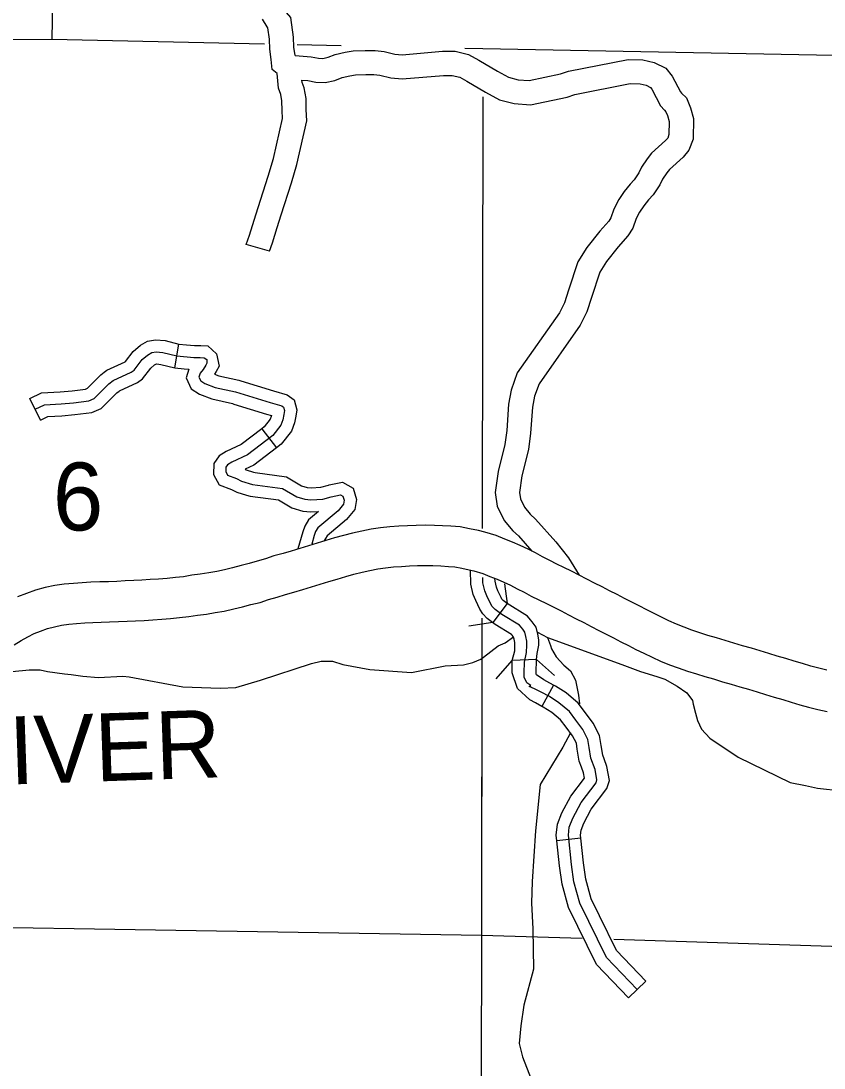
# Model space of a CAD drawing. Extents: x 0 to 3171, y 0 to 2059.
# Drawn here: x 1927.5 to 2010.8, y 478.3 to 586.9 of the extents above; entities that cross this region are included whole.
import ezdxf

# ---------------------------------------------------------------- set-up
doc = ezdxf.new("R2010")
doc.units = 0
for name, color, linetype in [('Level 10', 7, 'Continuous'), ('Level 35', 7, 'Continuous'), ('Level 38', 7, 'Continuous'), ('Level 4', 7, 'Continuous'), ('Level 45', 7, 'Continuous'), ('Level 46', 7, 'Continuous'), ('Level 5', 7, 'Continuous'), ('Level 8', 7, 'Continuous')]:
    doc.layers.add(name, color=color, linetype=linetype)

msp = doc.modelspace()

# ---------------------------------------------------------------- linework, layer by layer
at = {"layer": 'Level 10'}
for p, q in [((1939.18, 528.82), (1939.18, 528.82)), ((1939.41, 524.66), (1939.41, 524.66))]:
    msp.add_line(p, q, dxfattribs=at)
for points in [[(2011.07, 519.52), (2010.23, 519.73), (2009.39, 519.96), (2008.54, 520.21), (2007.67, 520.47), (2006.8, 520.73), (2005.92, 521), (2005.03, 521.27), (2004.14, 521.54), (2003.23, 521.81), (2002.32, 522.07), (2001.42, 522.34), (2000.52, 522.61), (1999.63, 522.88), (1998.73, 523.14), (1997.88, 523.4), (1997.06, 523.68), (1996.25, 523.98), (1995.46, 524.31), (1994.68, 524.65), (1993.92, 525.02), (1993.15, 525.4), (1992.38, 525.8), (1991.61, 526.19), (1990.85, 526.58), (1990.08, 526.97), (1989.31, 527.37), (1988.54, 527.76), (1987.77, 528.16), (1986.98, 528.57), (1986.19, 528.98), (1985.39, 529.4), (1984.59, 529.8), (1983.8, 530.18), (1983.06, 530.54), (1982.33, 530.92), (1981.59, 531.3), (1980.85, 531.69), (1980.08, 532.08), (1979.28, 532.46), (1978.46, 532.81), (1977.68, 533.12), (1976.77, 533.49), (1975.61, 533.83), (1974.94, 534.01), (1974.03, 534.2), (1973.05, 534.38), (1972.09, 534.46), (1971.23, 534.5), (1970.37, 534.54), (1969.43, 534.57), (1968.5, 534.55), (1967.6, 534.51), (1966.69, 534.46), (1965.76, 534.39), (1964.8, 534.28), (1963.82, 534.14), (1962.85, 533.96), (1961.88, 533.74), (1960.95, 533.5), (1960.03, 533.25), (1959.12, 532.98), (1958.22, 532.71), (1957.32, 532.43), (1956.43, 532.15), (1955.53, 531.89), (1954.69, 531.62), (1953.74, 531.38), (1952.87, 531.08), (1952, 530.85), (1951.17, 530.58), (1950.33, 530.38), (1949.45, 530.14), (1948.61, 529.93), (1947.83, 529.75), (1946.98, 529.63), (1946.11, 529.48), (1945.22, 529.37), (1944.35, 529.22), (1943.54, 529.13), (1942.66, 529.05), (1941.79, 528.97), (1940.92, 528.92), (1940.06, 528.86), (1939.2, 528.82)], [(1939.4, 524.66), (1940.3, 524.7), (1941.2, 524.76), (1942.11, 524.82), (1943.03, 524.9), (1943.95, 524.99), (1944.92, 525.09), (1945.82, 525.25), (1946.74, 525.35), (1947.65, 525.52), (1948.59, 525.65), (1949.57, 525.88), (1950.49, 526.11), (1951.36, 526.34), (1952.3, 526.56), (1953.18, 526.85), (1954.09, 527.09), (1954.94, 527.39), (1955.82, 527.61), (1956.75, 527.9), (1957.64, 528.17), (1958.54, 528.45), (1959.43, 528.72), (1960.31, 528.98), (1961.18, 529.24), (1962.03, 529.48), (1962.87, 529.69), (1963.69, 529.88), (1964.5, 530.03), (1965.31, 530.15), (1966.14, 530.24), (1966.97, 530.3), (1967.81, 530.35), (1968.63, 530.38), (1969.41, 530.4), (1970.21, 530.37), (1971.04, 530.34), (1971.82, 530.3), (1972.5, 530.24), (1973.23, 530.11), (1973.99, 529.95), (1974.48, 529.82), (1975.38, 529.55), (1976.12, 529.25), (1976.87, 528.96), (1977.56, 528.66), (1978.25, 528.34), (1978.94, 527.98), (1979.67, 527.61), (1980.41, 527.22), (1981.19, 526.82), (1981.98, 526.43), (1982.74, 526.06), (1983.5, 525.68), (1984.28, 525.28), (1985.06, 524.87), (1985.85, 524.46), (1986.63, 524.06), (1987.41, 523.66), (1988.19, 523.26), (1988.95, 522.87), (1989.71, 522.48), (1990.48, 522.08), (1991.27, 521.69), (1992.08, 521.28), (1992.94, 520.87), (1993.83, 520.47), (1994.74, 520.1), (1995.66, 519.76), (1996.6, 519.44), (1997.53, 519.16), (1998.42, 518.89), (1999.32, 518.62), (2000.24, 518.34), (2001.15, 518.08), (2002.05, 517.81), (2002.94, 517.55), (2003.82, 517.28), (2004.71, 517.01), (2005.59, 516.74), (2006.48, 516.48), (2007.36, 516.21), (2008.26, 515.95), (2009.17, 515.7), (2010.12, 515.47), (2011.09, 515.25)], [(1939.21, 528.82), (1938.31, 528.78), (1937.45, 528.73), (1936.59, 528.71), (1935.69, 528.68), (1934.77, 528.65), (1933.86, 528.59), (1932.95, 528.52), (1932.01, 528.44), (1931.02, 528.3), (1930.01, 528.09), (1929.03, 527.82), (1928.1, 527.5), (1927.15, 527.13)], [(1926.81, 522.17), (1927.53, 522.61), (1928.23, 522.99), (1928.88, 523.33), (1929.55, 523.59), (1930.27, 523.84), (1930.99, 524.04), (1931.72, 524.2), (1932.48, 524.3), (1933.29, 524.37), (1934.14, 524.43), (1934.98, 524.49), (1935.83, 524.52), (1936.71, 524.54), (1937.62, 524.57), (1938.51, 524.62), (1939.38, 524.65)]]:
    msp.add_lwpolyline(points, dxfattribs=at)
at = {"layer": 'Level 35'}
for points in [[(1981.05, 523.48), (1982.1, 522.93), (1989.79, 520.12), (1991.75, 519.41), (1993.42, 518.88), (1994.25, 518.6), (1995.53, 517.89), (1996.53, 517.18), (1997.12, 516.4), (1997.2, 516.01), (1997.45, 515.06), (1997.64, 514.31), (1998.05, 513.43), (1998.93, 512.5), (2001.87, 510.51), (2007.26, 507.88), (2008.84, 507.57), (2010.08, 507.31), (2012.6, 507.02), (2014.93, 507.07), (2016.45, 507.19), (2019.17, 507.95), (2021.33, 509.21)], [(1975.19, 520.69), (1975.48, 520.87), (1976.99, 522.04), (1977.71, 522.37), (1978.57, 522.99)], [(1982.1, 522.93), (1982.42, 522.09), (1982.51, 521.76), (1983, 520.92), (1983.8, 520.04), (1984.48, 519.45), (1984.99, 518.49), (1985.32, 516.94), (1985.4, 516.03)], [(1926.59, 519.41), (1928.35, 519.58), (1929.52, 519.58), (1930.28, 519.41), (1932.04, 519.17), (1932.71, 519.09), (1933.94, 518.9), (1935.55, 518.77), (1938.09, 518.91), (1938.72, 518.86), (1944.31, 517.79), (1948.17, 517.66), (1949.78, 517.73), (1952.34, 518.49), (1957.65, 520.24), (1958.65, 520.48), (1959.81, 520.46), (1960.89, 520.11), (1963.69, 519.6), (1968.01, 519.3), (1971.49, 520), (1973.4, 520.1), (1974.37, 520.33), (1975.19, 520.69)], [(1984.48, 513.02), (1983.7, 511.56), (1981.33, 507.68), (1980.86, 502.87), (1980.52, 497.61), (1980.43, 495.36), (1980.57, 492.71), (1980.64, 488.52), (1979.66, 484.81), (1979.32, 482.64), (1979.17, 480.81), (1979.52, 479.45), (1980.83, 476.04), (1981.37, 473.83), (1981.62, 472.18), (1981.95, 470.65), (1982.6, 468.76)]]:
    msp.add_lwpolyline(points, dxfattribs=at)
at = {"layer": 'Level 38'}
for points in [[(1977.64, 528.47), (1977.92, 526.46)], [(1976.42, 524.46), (1973.95, 524.1)], [(1976.78, 518.65), (1978.45, 520.52)], [(1980.95, 520.65), (1982.81, 518.98)]]:
    msp.add_lwpolyline(points, dxfattribs=at)
at = {"layer": 'Level 4'}
for points in [[(1931.3, 619.32), (1930.73, 584.94)], [(1930.73, 584.94), (1886.47, 584.79)], [(1952.76, 584.45), (1930.73, 584.94)], [(1960.72, 584.28), (1956.16, 584.38)], [(2027.43, 583.03), (2019.09, 583.13), (1975.39, 583.96), (1973.52, 584)]]:
    msp.add_lwpolyline(points, dxfattribs=at)
at = {"layer": 'Level 45'}
for p, q in [((1943.47, 550.88), (1943.89, 553.35)), ((1929.53, 545.45), (1928.44, 547.7)), ((1952.48, 544.57), (1954, 542.58)), ((1977.92, 526.46), (1976.42, 524.46)), ((1980.95, 520.65), (1978.45, 520.52)), ((1982.71, 517.98), (1981.52, 515.78)), ((1985.55, 502.12), (1983.07, 501.85)), ((1992.3, 487.28), (1990.5, 485.55))]:
    msp.add_line(p, q, dxfattribs=at)
for points in [[(1936.13, 550.42), (1936.42, 550.65), (1938.32, 551.52), (1938.36, 551.55), (1939.15, 552.59), (1939.91, 553.23), (1940.63, 553.65), (1941.47, 553.8), (1942.45, 553.72), (1943.89, 553.35), (1944.68, 553.28)], [(1944.68, 553.28), (1945.5, 553.21), (1946.16, 553.21), (1946.9, 553.15), (1947.77, 552.34), (1948.05, 551.04), (1947.75, 550.51), (1947.57, 550.23), (1948.02, 550.06), (1950.09, 549.59), (1950.32, 549.52)], [(1928.99, 546.58), (1929.97, 547.05), (1931.67, 547.14), (1932.95, 547.27), (1934.55, 547.46), (1935.11, 547.71), (1936.63, 549.22), (1937.08, 549.57), (1938.95, 550.43), (1939.25, 550.65), (1940.07, 551.73), (1940.63, 552.21), (1941.07, 552.46), (1941.53, 552.54), (1942.24, 552.48), (1943.68, 552.12), (1945.45, 551.96), (1946.11, 551.96), (1946.52, 551.93), (1946.8, 551.76), (1946.8, 551.36), (1946.69, 551.16), (1946.39, 550.71), (1946.1, 550.34), (1945.97, 549.93), (1946.15, 549.55), (1946.59, 549.27), (1947.66, 548.86), (1949.76, 548.38), (1953.34, 547.29), (1954.57, 546.94), (1954.73, 546.82), (1954.82, 546.47), (1954.77, 546.06), (1954.67, 545.5), (1954.46, 544.95), (1953.61, 543.86), (1951, 541.85), (1949.38, 541.1), (1948.93, 540.83), (1948.75, 540.57), (1948.74, 540.12), (1948.94, 539.77), (1949.85, 539.42), (1950.38, 539.14), (1951.52, 538.8), (1954.64, 538.38), (1956.1, 537.5), (1956.95, 537.25), (1957.58, 537.2), (1958.81, 537.26), (1959.68, 537.52), (1960.63, 537.7), (1960.89, 537.56), (1961.01, 537.15), (1960.94, 536.73), (1960.39, 536.05), (1958.3, 534.3), (1958.06, 533.9), (1957.91, 533.5), (1957.67, 532.61)], [(1937.68, 548.46), (1937.73, 548.5), (1939.59, 549.35), (1940.13, 549.75), (1940.98, 550.86), (1941.36, 551.18), (1941.5, 551.27), (1941.59, 551.28), (1942.03, 551.24), (1943.47, 550.88), (1944.45, 550.79)], [(1944.45, 550.79), (1944.92, 550.75), (1944.63, 549.84), (1945.17, 548.69), (1946.02, 548.15), (1947.3, 547.66), (1949.44, 547.17), (1949.59, 547.13)], [(1928.44, 547.7), (1929.65, 548.29), (1931.58, 548.39), (1932.82, 548.51), (1934.22, 548.68), (1934.4, 548.76), (1935.8, 550.16), (1936.13, 550.42)], [(1950.32, 549.52), (1953.69, 548.49), (1955.12, 548.08), (1955.83, 547.57), (1956.1, 546.54), (1956, 545.87), (1955.88, 545.17), (1955.56, 544.33), (1954.5, 542.96), (1954, 542.58)], [(1929.53, 545.45), (1930.29, 545.82), (1931.76, 545.9), (1933.09, 546.03), (1934.88, 546.24), (1935.83, 546.66), (1937.46, 548.29), (1937.68, 548.46)], [(1949.59, 547.13), (1952.98, 546.09), (1953.48, 545.95), (1953.46, 545.84), (1953.36, 545.57), (1952.73, 544.75), (1952.48, 544.57)], [(1952.48, 544.57), (1950.35, 542.93), (1948.79, 542.21), (1948.05, 541.76), (1947.51, 540.97), (1947.48, 539.81), (1948.08, 538.76), (1949.34, 538.28), (1949.91, 537.98), (1950.89, 537.68)], [(1954, 542.58), (1951.65, 540.78), (1950.75, 540.36), (1950.86, 540.31), (1951.62, 540.08)], [(1951.62, 540.08), (1951.79, 540.02), (1955.06, 539.59), (1956.61, 538.65), (1957.18, 538.48), (1957.6, 538.45), (1958.6, 538.5), (1959.38, 538.73), (1959.45, 538.74)], [(1959.45, 538.74), (1960.84, 539.02), (1961.96, 538.4), (1962.29, 537.22), (1962.11, 536.19), (1961.28, 535.17), (1959.27, 533.48), (1958.93, 532.92)], [(1950.89, 537.68), (1951.26, 537.57), (1954.22, 537.18), (1955.6, 536.35), (1956.72, 536.01), (1957.56, 535.94), (1958.37, 535.99)], [(1958.37, 535.99), (1957.34, 535.12), (1956.93, 534.45), (1956.72, 533.89), (1956.23, 532.1)], [(1978.42, 523.17), (1978.37, 523.23), (1976.68, 524.26), (1975.83, 524.9), (1975.39, 525.38), (1975.09, 525.85), (1974.66, 526.75), (1974.41, 527.39), (1974.16, 528.44), (1974.12, 529.92)], [(1991.4, 486.42), (1988.2, 489.75), (1985.46, 495.39), (1984.84, 497.6), (1984.59, 499.4), (1984.26, 502.43), (1984.35, 503.25), (1984.74, 504.2), (1985.58, 505.8), (1987.13, 507.85), (1987.23, 508.17), (1987.04, 509.22), (1986.6, 510.41), (1986.42, 511.52), (1986.29, 512.36), (1985.76, 513.38), (1985.05, 514.36), (1984.37, 515.26), (1983.29, 516.16), (1982.29, 516.79), (1981.43, 517.25), (1980.76, 517.61), (1980.21, 517.85), (1980.36, 517.94), (1979.96, 518.22), (1979.69, 518.82), (1979.68, 519.27), (1979.7, 520.36), (1979.94, 521.38), (1979.96, 522.13), (1979.95, 522.55), (1979.86, 523.02), (1979.75, 523.48), (1979.53, 523.79), (1979.2, 524.19), (1977.38, 525.3), (1976.67, 525.83), (1976.38, 526.14), (1976.19, 526.45), (1975.81, 527.25), (1975.61, 527.76), (1975.41, 528.6), (1975.4, 529.13)], [(1980.34, 524.77), (1980.03, 525.15), (1977.92, 526.46), (1977.51, 526.77), (1977.38, 526.91), (1977.29, 527.06), (1976.96, 527.75), (1976.8, 528.14), (1976.66, 528.77), (1976.65, 529.05)], [(1982.71, 517.98), (1982.02, 518.35), (1981.71, 518.52), (1980.96, 519.05), (1980.93, 519.11), (1980.93, 519.27), (1980.95, 520.65), (1981.04, 521.26), (1981.21, 522.13), (1981.2, 522.69), (1981.09, 523.28), (1980.91, 524.01), (1980.52, 524.56), (1980.34, 524.77)], [(1981.52, 515.78), (1980.84, 516.15), (1980.27, 516.45), (1978.99, 517.65), (1978.42, 519.26), (1978.45, 520.52), (1978.7, 521.54), (1978.71, 522.13), (1978.71, 522.42), (1978.64, 522.75), (1978.59, 522.95), (1978.54, 523.03), (1978.42, 523.17)], [(1987.97, 510.33), (1987.82, 510.73), (1987.66, 511.72), (1987.49, 512.76), (1986.82, 514.04), (1986.05, 515.1), (1985.29, 516.12), (1984.02, 517.18), (1982.92, 517.87), (1982.71, 517.98)], [(1985.62, 509.46), (1985.39, 510.09), (1985.19, 511.33), (1985.09, 511.97), (1984.69, 512.72), (1984.04, 513.62), (1983.46, 514.39), (1982.55, 515.15), (1981.66, 515.7), (1981.52, 515.78)], [(1985.55, 502.12), (1985.52, 502.43), (1985.58, 502.94), (1985.87, 503.68), (1986.64, 505.13), (1988.26, 507.27), (1988.52, 508.1), (1988.25, 509.55), (1987.97, 510.33)], [(1983.07, 501.85), (1983.01, 502.43), (1983.13, 503.56), (1983.6, 504.73), (1984.52, 506.47), (1985.93, 508.33), (1985.83, 508.88), (1985.62, 509.46)], [(1985.25, 492.96), (1984.29, 494.94), (1983.61, 497.35), (1983.35, 499.24), (1983.07, 501.85)], [(1987.5, 494.06), (1986.63, 495.83), (1986.07, 497.86), (1985.83, 499.55), (1985.55, 502.12)], [(1992.3, 487.28), (1989.24, 490.48), (1987.5, 494.06)], [(1990.5, 485.55), (1987.17, 489.03), (1985.25, 492.96)]]:
    msp.add_lwpolyline(points, dxfattribs=at)
at = {"layer": 'Level 46'}
for points in [[(1955.93, 583.27), (1955.82, 584.13), (1955.78, 585.18), (1955.5, 587.22), (1955.06, 587.73), (1954.95, 587.9), (1954.9, 588.33), (1954.79, 589.65), (1954.94, 590.17), (1955.07, 591.92), (1955.13, 594.07), (1954.75, 600.34)], [(1954.06, 581.4), (1953.55, 581.81), (1953.46, 582.85), (1953.33, 583.92), (1953.28, 584.96), (1953.12, 586.15), (1953.04, 586.24), (1952.54, 587.04)], [(1955.93, 583.27), (1957.61, 583.14), (1958.37, 582.98), (1958.82, 582.97), (1959.36, 583.08), (1960.08, 583.36), (1961.11, 583.6), (1961.94, 583.74), (1963.21, 583.79), (1964.23, 583.79), (1965.16, 583.68), (1966.26, 583.42), (1967.05, 583.35), (1971.22, 583.7), (1972.54, 583.7), (1973.9, 583.37), (1974.97, 582.8), (1976.91, 581.65), (1978.07, 581.01), (1979.06, 580.76), (1980.19, 580.67), (1983.45, 581.36), (1984.27, 581.65), (1990.46, 582.85), (1991.99, 582.83), (1993.17, 582.55), (1994.36, 581.96), (1995.04, 581.13), (1995.87, 579.49), (1996, 579.35), (1996.5, 578.89), (1996.91, 577.84), (1997.22, 576.73), (1997.19, 574.6), (1996.75, 573.44), (1996.16, 572.71), (1994.73, 571.44), (1994.46, 571.09), (1994.03, 570.45), (1993.75, 569.86), (1993.05, 568.83), (1992.57, 568.3), (1992.08, 567.68), (1991.64, 567.03), (1991.28, 566.36), (1990.96, 565.35), (1990.43, 564.56), (1989.43, 563.43), (1988.23, 561.92), (1987.54, 560.8), (1986.66, 558.16), (1986.19, 556.68), (1985.49, 555.3), (1981.22, 549.23), (1980.76, 547.93), (1980.55, 546.8), (1980.35, 544.11), (1980.12, 542.4)], [(1953.27, 562.98), (1950.87, 563.67), (1951.21, 564.64), (1951.7, 566.18), (1952.12, 567.5), (1953.16, 570.77), (1953.68, 572.59), (1954.63, 576.72), (1954.59, 577.58), (1954.57, 578.58), (1954.47, 579.24), (1954.21, 579.87), (1954.06, 581.4)], [(1953.27, 562.98), (1953.58, 563.85), (1954.08, 565.42), (1954.5, 566.75), (1955.56, 570.05), (1956.1, 571.97), (1957.15, 576.49), (1957.09, 577.67), (1957.07, 578.81), (1956.89, 579.91), (1956.67, 580.47), (1956.64, 580.71), (1957.26, 580.66), (1958.07, 580.49), (1959.04, 580.46), (1960.07, 580.68), (1960.82, 580.97), (1961.6, 581.15), (1962.2, 581.25), (1963.26, 581.29), (1964.08, 581.29), (1964.72, 581.22), (1965.86, 580.95), (1967.04, 580.84), (1971.32, 581.2), (1972.23, 581.2), (1973.02, 581.01), (1973.75, 580.62), (1975.66, 579.48), (1977.14, 578.66), (1978.65, 578.29), (1980.35, 578.15), (1984.13, 578.95), (1984.92, 579.23), (1990.68, 580.35), (1991.69, 580.34), (1992.32, 580.19), (1992.77, 579.96), (1992.93, 579.76), (1993.8, 578.06), (1994.22, 577.59), (1994.38, 577.44), (1994.54, 577.05), (1994.71, 576.41), (1994.69, 575.07), (1994.56, 574.7), (1994.34, 574.44), (1992.88, 573.14), (1992.43, 572.54), (1991.86, 571.7), (1991.57, 571.11), (1991.08, 570.38), (1990.66, 569.91), (1990.06, 569.16), (1989.5, 568.33), (1988.96, 567.34), (1988.68, 566.44), (1988.45, 566.09), (1987.51, 565.04), (1986.18, 563.36), (1985.26, 561.87), (1984.28, 558.93), (1983.87, 557.63), (1983.34, 556.6), (1978.97, 550.38), (1978.34, 548.57), (1978.07, 547.12), (1977.87, 544.37), (1977.67, 542.93)], [(1977.67, 542.93), (1976.97, 540.12), (1976.68, 537.97), (1976.87, 536.55), (1977.61, 535.06), (1978.49, 533.99), (1979.08, 533.45), (1980.48, 531.89)], [(1980.12, 542.4), (1979.44, 539.69), (1979.2, 537.97), (1979.3, 537.29), (1979.72, 536.43), (1980.31, 535.72), (1980.86, 535.2), (1982.97, 532.85), (1984.28, 531.18), (1985.39, 529.4)]]:
    msp.add_lwpolyline(points, dxfattribs=at)
at = {"layer": 'Level 5'}
for points in [[(1975.38, 578.98), (1975.32, 534.23)], [(1975.3, 524.94), (1975.26, 492.07)], [(1886.52, 493.51), (1975.26, 492.07)], [(1975.26, 492.07), (1985.71, 491.73)], [(1988.98, 491.63), (2064.15, 489.21)]]:
    msp.add_lwpolyline(points, dxfattribs=at)
at = {"layer": 'Level 8'}
msp.add_lwpolyline([(1975.3, 520.76), (1975.26, 492.07), (1975.04, 404.29), (1997.41, 403.34), (1997.5, 425.42)], dxfattribs=at)

# ---------------------------------------------------------------- texts
at = {"layer": 'Level 35'}
msp.add_text('RIVER', height=7.04, rotation=1.9835, dxfattribs=at).set_placement((1919.59, 507.44))
at = {"layer": 'Level 5'}
msp.add_text('6', height=7.04, dxfattribs=at).set_placement((1930.82, 534.02))

doc.saveas('drawing.dxf')
